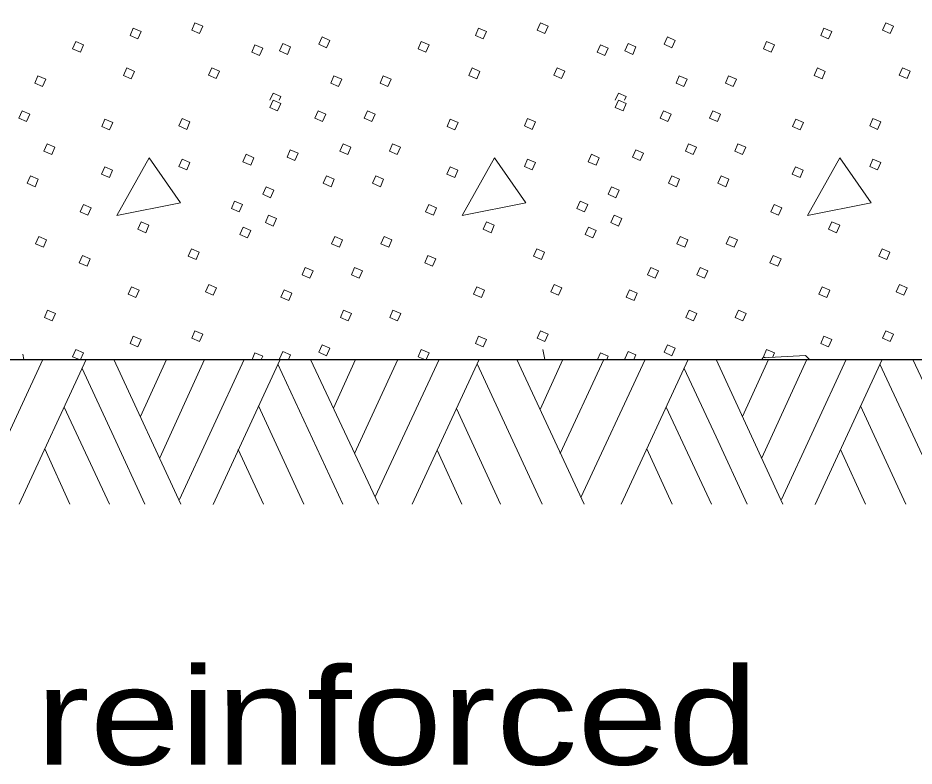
# Model space of a CAD drawing. Extents: x 1083.1 to 1117.1, y 697.4 to 741.4.
# Drawn here: x 1092.828 to 1094.266, y 720.549 to 721.75 of the extents above; entities that cross this region are included whole.
import ezdxf

# ---------------------------------------------------------------- set-up
doc = ezdxf.new("R2010")
doc.units = 0
doc.header["$LTSCALE"] = 0.062
doc.layers.add('1', color=7, linetype='Continuous', lineweight=13)

msp = doc.modelspace()

# ---------------------------------------------------------------- linework, layer by layer
at = {"layer": '1'}
for p, q in [((1093.23258, 721.61833), (1093.23758, 721.62975)), ((1093.78692, 721.61833), (1093.79192, 721.62975)), ((1092.8375, 721.20167), (1092.83575, 721.21042)), ((1093.20392, 721.20167), (1093.20858, 721.2125)), ((1093.67367, 721.20167), (1093.67058, 721.21775)), ((1093.75817, 721.20167), (1093.76292, 721.2125)), ((1092.86833, 721.20167), (1092.76533, 720.9805)), ((1092.9375, 721.20167), (1092.83017, 720.96958)), ((1092.98225, 721.20167), (1093.08958, 720.96958)), ((1093.06658, 721.20167), (1093.02467, 721.11017)), ((1093.12775, 721.20167), (1093.05567, 721.04392)), ((1093.19125, 721.20167), (1093.0875, 720.97683)), ((1093.24892, 721.20167), (1093.14142, 720.96892)), ((1093.24525, 721.1945), (1093.34975, 720.96958)), ((1093.29783, 721.20167), (1093.40675, 720.96958)), ((1093.36992, 721.20167), (1093.33467, 721.12383)), ((1093.43767, 721.20167), (1093.36842, 721.05108)), ((1093.504, 721.20167), (1093.40158, 720.98125)), ((1093.56817, 721.20167), (1093.46067, 720.96958)), ((1093.56525, 721.19517), (1093.66967, 720.96958)), ((1093.62858, 721.20167), (1093.73675, 720.96958)), ((1093.70292, 721.20167), (1093.66608, 721.12175)), ((1093.76842, 721.20167), (1093.69858, 721.05108)), ((1093.83475, 721.20167), (1093.73167, 720.9805)), ((1093.904, 721.20167), (1093.7965, 720.96958)), ((1093.94858, 721.20167), (1094.056, 720.96958)), ((1094.03292, 721.20167), (1093.99117, 721.11017)), ((1094.09417, 721.20167), (1094.02217, 721.04392)), ((1094.15758, 721.20167), (1094.05383, 720.97683)), ((1094.21525, 721.20167), (1094.10792, 720.96892)), ((1094.21167, 721.1945), (1094.31617, 720.96958)), ((1094.26425, 721.20167), (1094.37308, 720.96958)), ((1092.93108, 721.18733), (1092.98225, 721.07775)), ((1093.8975, 721.18733), (1093.94858, 721.07775)), ((1092.90225, 721.12533), (1092.975, 720.96958)), ((1093.21433, 721.12742), (1093.28708, 720.96958)), ((1093.53208, 721.12317), (1093.60275, 720.96958)), ((1093.86858, 721.12533), (1093.94133, 720.96958)), ((1094.18067, 721.12742), (1094.25342, 720.96958)), ((1092.98225, 721.07775), (1093.032, 720.96958)), ((1093.94858, 721.07775), (1093.99833, 720.96958)), ((1092.87125, 721.05825), (1092.91158, 720.96958)), ((1093.18183, 721.05758), (1093.22217, 720.96958)), ((1093.50175, 721.05533), (1093.54075, 720.96958)), ((1093.83758, 721.05825), (1093.878, 720.96958)), ((1094.14825, 721.05758), (1094.18858, 720.96958))]:
    msp.add_line(p, q, dxfattribs=at)
at = {"layer": '1', "lineweight": 25}
for points in [[(1091.06575, 722.92817), (1090.41717, 722.92817), (1090.41717, 721.20167), (1094.915, 721.20167), (1094.915, 722.92817)], [(1090.41717, 722.92817), (1090.41717, 721.20167), (1094.915, 721.20167), (1094.915, 722.92817), (1094.26642, 722.92817)]]:
    msp.add_lwpolyline(points, dxfattribs=at)
at = {"layer": '1'}
for points in [[(1093.11225, 721.74233), (1093.12475, 721.73692), (1093.11958, 721.72517), (1093.10708, 721.7305)], [(1093.66658, 721.74233), (1093.67908, 721.73692), (1093.67392, 721.72517), (1093.66142, 721.7305)], [(1094.22083, 721.74233), (1094.23333, 721.73692), (1094.22817, 721.72517), (1094.21567, 721.7305)], [(1093.01317, 721.734), (1093.02567, 721.72858), (1093.0205, 721.71683), (1093.008, 721.72225)], [(1093.5675, 721.734), (1093.58, 721.72858), (1093.57483, 721.71683), (1093.56233, 721.72225)], [(1094.12183, 721.734), (1094.13433, 721.72858), (1094.12917, 721.71683), (1094.11667, 721.72225)], [(1092.92108, 721.71267), (1092.93358, 721.70725), (1092.92842, 721.69542), (1092.91592, 721.70083)], [(1093.31625, 721.71975), (1093.32875, 721.71433), (1093.32358, 721.7025), (1093.31108, 721.70792)], [(1093.47542, 721.71267), (1093.48792, 721.70725), (1093.48275, 721.69542), (1093.47025, 721.70083)], [(1093.8705, 721.71975), (1093.883, 721.71433), (1093.87783, 721.7025), (1093.86533, 721.70792)], [(1094.02967, 721.71267), (1094.04217, 721.70725), (1094.037, 721.69542), (1094.02458, 721.70083)], [(1093.20858, 721.707), (1093.22108, 721.70158), (1093.21592, 721.68975), (1093.20342, 721.69517)], [(1093.25317, 721.70908), (1093.26567, 721.70367), (1093.2605, 721.69183), (1093.248, 721.69725)], [(1093.76292, 721.707), (1093.77542, 721.70158), (1093.77025, 721.68975), (1093.75775, 721.69517)], [(1093.8075, 721.70908), (1093.82, 721.70367), (1093.81483, 721.69183), (1093.80233, 721.69725)], [(1093.00275, 721.66992), (1093.01525, 721.6645), (1093.01008, 721.65267), (1092.99758, 721.65808)], [(1093.13917, 721.67017), (1093.15167, 721.66475), (1093.1465, 721.65292), (1093.134, 721.65833)], [(1093.55708, 721.66992), (1093.56958, 721.6645), (1093.56442, 721.65267), (1093.55192, 721.65808)], [(1093.69342, 721.67017), (1093.70592, 721.66475), (1093.70075, 721.65292), (1093.68825, 721.65833)], [(1094.11142, 721.66992), (1094.12392, 721.6645), (1094.11875, 721.65267), (1094.10625, 721.65808)], [(1094.24775, 721.67017), (1094.26025, 721.66475), (1094.25508, 721.65292), (1094.24258, 721.65833)], [(1092.86017, 721.65742), (1092.87267, 721.652), (1092.8675, 721.64017), (1092.855, 721.64558)], [(1093.33525, 721.65742), (1093.34775, 721.652), (1093.34258, 721.64017), (1093.33008, 721.64558)], [(1093.4145, 721.65742), (1093.427, 721.652), (1093.42183, 721.64017), (1093.40933, 721.64558)], [(1093.88958, 721.65742), (1093.90208, 721.652), (1093.89692, 721.64017), (1093.88442, 721.64558)], [(1093.96883, 721.65742), (1093.98133, 721.652), (1093.97617, 721.64017), (1093.96367, 721.64558)], [(1093.23758, 721.61833), (1093.25008, 721.61292), (1093.24492, 721.60108), (1093.23242, 721.6065)], [(1093.79192, 721.61833), (1093.80442, 721.61292), (1093.79925, 721.60108), (1093.78675, 721.6065)], [(1092.83467, 721.60133), (1092.84717, 721.59592), (1092.842, 721.58417), (1092.8295, 721.5895)], [(1093.30983, 721.60133), (1093.32233, 721.59592), (1093.31717, 721.58417), (1093.30467, 721.5895)], [(1093.389, 721.60133), (1093.4015, 721.59592), (1093.39633, 721.58417), (1093.38383, 721.5895)], [(1093.86408, 721.60133), (1093.87658, 721.59592), (1093.87142, 721.58417), (1093.85892, 721.5895)], [(1093.94333, 721.60133), (1093.95583, 721.59592), (1093.95067, 721.58417), (1093.93817, 721.5895)], [(1092.96783, 721.58792), (1092.98025, 721.58258), (1092.97517, 721.57075), (1092.96267, 721.57617)], [(1093.09175, 721.58858), (1093.10425, 721.58325), (1093.09908, 721.57142), (1093.08658, 721.57683)], [(1093.52208, 721.58792), (1093.53458, 721.58258), (1093.52942, 721.57075), (1093.51692, 721.57617)], [(1093.64608, 721.58858), (1093.65858, 721.58325), (1093.65342, 721.57142), (1093.64092, 721.57683)], [(1094.07642, 721.58792), (1094.08892, 721.58258), (1094.08375, 721.57075), (1094.07125, 721.57617)], [(1094.20042, 721.58858), (1094.21283, 721.58325), (1094.20775, 721.57142), (1094.19525, 721.57683)], [(1092.87508, 721.54833), (1092.88758, 721.54292), (1092.88242, 721.53108), (1092.86992, 721.5365)], [(1093.26525, 721.53842), (1093.27775, 721.533), (1093.27258, 721.52117), (1093.26008, 721.52658)], [(1093.35017, 721.54833), (1093.36267, 721.54292), (1093.3575, 721.53108), (1093.345, 721.5365)], [(1093.42942, 721.54833), (1093.44192, 721.54292), (1093.43675, 721.53108), (1093.42425, 721.5365)], [(1093.81958, 721.53842), (1093.83208, 721.533), (1093.82692, 721.52117), (1093.81442, 721.52658)], [(1093.9045, 721.54833), (1093.917, 721.54292), (1093.91183, 721.53108), (1093.89933, 721.5365)], [(1093.98375, 721.54833), (1093.99625, 721.54292), (1093.99108, 721.53108), (1093.97858, 721.5365)], [(1093.03883, 721.52592), (1092.98658, 721.43333), (1093.08892, 721.45325)], [(1093.19442, 721.53133), (1093.20692, 721.52592), (1093.20175, 721.51408), (1093.18925, 721.5195)], [(1093.59317, 721.52592), (1093.54092, 721.43333), (1093.64325, 721.45325)], [(1093.74875, 721.53133), (1093.76125, 721.52592), (1093.75608, 721.51408), (1093.74358, 721.5195)], [(1094.1475, 721.52592), (1094.09525, 721.43333), (1094.19758, 721.45325)], [(1092.96758, 721.51125), (1092.98, 721.50583), (1092.97483, 721.494), (1092.96242, 721.49942)], [(1093.09175, 721.5235), (1093.10425, 721.51808), (1093.09908, 721.50625), (1093.08658, 721.51167)], [(1093.52183, 721.51125), (1093.53433, 721.50583), (1093.52917, 721.494), (1093.51667, 721.49942)], [(1093.64608, 721.5235), (1093.65858, 721.51808), (1093.65342, 721.50625), (1093.64092, 721.51167)], [(1094.07617, 721.51125), (1094.08867, 721.50583), (1094.0835, 721.494), (1094.071, 721.49942)], [(1094.20042, 721.5235), (1094.21283, 721.51808), (1094.20775, 721.50625), (1094.19525, 721.51167)], [(1092.84817, 721.49658), (1092.86067, 721.49117), (1092.8555, 721.47933), (1092.843, 721.48475)], [(1093.32333, 721.49658), (1093.33575, 721.49117), (1093.33058, 721.47933), (1093.31817, 721.48475)], [(1093.4025, 721.49658), (1093.415, 721.49117), (1093.40983, 721.47933), (1093.39733, 721.48475)], [(1093.87758, 721.49658), (1093.89008, 721.49117), (1093.88492, 721.47933), (1093.87242, 721.48475)], [(1093.95683, 721.49658), (1093.96933, 721.49117), (1093.96417, 721.47933), (1093.95167, 721.48475)], [(1093.22625, 721.47892), (1093.23875, 721.4735), (1093.23358, 721.46167), (1093.22108, 721.46708)], [(1093.78058, 721.47892), (1093.79308, 721.4735), (1093.78792, 721.46167), (1093.77542, 721.46708)], [(1093.17592, 721.45625), (1093.18842, 721.45083), (1093.18325, 721.43908), (1093.17075, 721.44442)], [(1093.73025, 721.45625), (1093.74275, 721.45083), (1093.73758, 721.43908), (1093.72508, 721.44442)], [(1092.93317, 721.45058), (1092.94567, 721.44517), (1092.9405, 721.43342), (1092.928, 721.43883)], [(1093.4875, 721.45058), (1093.5, 721.44517), (1093.49483, 721.43342), (1093.48233, 721.43883)], [(1094.04175, 721.45058), (1094.05425, 721.44517), (1094.04908, 721.43342), (1094.03658, 721.43883)], [(1093.2305, 721.43342), (1093.243, 721.428), (1093.23783, 721.41617), (1093.22533, 721.42158)], [(1093.78483, 721.43342), (1093.79733, 721.428), (1093.79217, 721.41617), (1093.77967, 721.42158)], [(1093.02583, 721.42275), (1093.03833, 721.41733), (1093.03317, 721.4055), (1093.02067, 721.41092)], [(1093.18942, 721.41425), (1093.20192, 721.40883), (1093.19675, 721.397), (1093.18425, 721.40242)], [(1093.58017, 721.42275), (1093.59267, 721.41733), (1093.5875, 721.4055), (1093.575, 721.41092)], [(1093.74375, 721.41425), (1093.75625, 721.40883), (1093.75108, 721.397), (1093.73858, 721.40242)], [(1094.1345, 721.42275), (1094.147, 721.41733), (1094.14183, 721.4055), (1094.12933, 721.41092)], [(1092.86158, 721.39942), (1092.87408, 721.394), (1092.86892, 721.38217), (1092.85642, 721.38758)], [(1093.33667, 721.39942), (1093.34917, 721.394), (1093.344, 721.38217), (1093.3315, 721.38758)], [(1093.41592, 721.39942), (1093.42842, 721.394), (1093.42325, 721.38217), (1093.41075, 721.38758)], [(1093.891, 721.39942), (1093.9035, 721.394), (1093.89833, 721.38217), (1093.88583, 721.38758)], [(1093.97025, 721.39942), (1093.98275, 721.394), (1093.97758, 721.38217), (1093.96508, 721.38758)], [(1092.93175, 721.36892), (1092.94425, 721.3635), (1092.93908, 721.35167), (1092.92658, 721.35708)], [(1093.10658, 721.37958), (1093.11908, 721.37417), (1093.11392, 721.36233), (1093.10142, 721.36775)], [(1093.48608, 721.36892), (1093.49858, 721.3635), (1093.49342, 721.35167), (1093.48092, 721.35708)], [(1093.66092, 721.37958), (1093.67342, 721.37417), (1093.66825, 721.36233), (1093.65575, 721.36775)], [(1094.04033, 721.36892), (1094.05283, 721.3635), (1094.04767, 721.35167), (1094.03517, 721.35708)], [(1094.21517, 721.37958), (1094.22767, 721.37417), (1094.2225, 721.36233), (1094.21, 721.36775)], [(1093.28933, 721.34983), (1093.30183, 721.34442), (1093.29667, 721.33258), (1093.28417, 721.338)], [(1093.3685, 721.34983), (1093.381, 721.34442), (1093.37583, 721.33258), (1093.36333, 721.338)], [(1093.84367, 721.34983), (1093.85617, 721.34442), (1093.851, 721.33258), (1093.8385, 721.338)], [(1093.92283, 721.34983), (1093.93533, 721.34442), (1093.93017, 721.33258), (1093.91767, 721.338)], [(1093.01025, 721.31867), (1093.02275, 721.31325), (1093.01758, 721.30142), (1093.00508, 721.30683)], [(1093.13425, 721.32217), (1093.14675, 721.31675), (1093.14158, 721.30492), (1093.12908, 721.31033)], [(1093.25533, 721.31367), (1093.26783, 721.30825), (1093.26267, 721.2965), (1093.25017, 721.30183)], [(1093.56458, 721.31867), (1093.57708, 721.31325), (1093.57192, 721.30142), (1093.55942, 721.30683)], [(1093.6885, 721.32217), (1093.701, 721.31675), (1093.69583, 721.30492), (1093.68333, 721.31033)], [(1093.80967, 721.31367), (1093.82217, 721.30825), (1093.817, 721.2965), (1093.8045, 721.30183)], [(1094.11892, 721.31867), (1094.13142, 721.31325), (1094.12625, 721.30142), (1094.11375, 721.30683)], [(1094.24283, 721.32217), (1094.25533, 721.31675), (1094.25017, 721.30492), (1094.23767, 721.31033)], [(1092.87575, 721.28117), (1092.88825, 721.27575), (1092.88308, 721.26392), (1092.87058, 721.26933)], [(1093.35083, 721.28117), (1093.36333, 721.27575), (1093.35817, 721.26392), (1093.34567, 721.26933)], [(1093.43008, 721.28117), (1093.44258, 721.27575), (1093.43742, 721.26392), (1093.42492, 721.26933)], [(1093.90517, 721.28117), (1093.91767, 721.27575), (1093.9125, 721.26392), (1093.9, 721.26933)], [(1093.98442, 721.28117), (1093.99692, 721.27575), (1093.99175, 721.26392), (1093.97925, 721.26933)], [(1093.01317, 721.23958), (1093.02567, 721.23417), (1093.0205, 721.22233), (1093.008, 721.22775)], [(1093.11225, 721.24792), (1093.12475, 721.2425), (1093.11958, 721.23067), (1093.10708, 721.23608)], [(1093.5675, 721.23958), (1093.58, 721.23417), (1093.57483, 721.22233), (1093.56233, 721.22775)], [(1093.66658, 721.24792), (1093.67908, 721.2425), (1093.67392, 721.23067), (1093.66142, 721.23608)], [(1094.12183, 721.23958), (1094.13433, 721.23417), (1094.12917, 721.22233), (1094.11667, 721.22775)], [(1094.22083, 721.24792), (1094.23333, 721.2425), (1094.22817, 721.23067), (1094.21567, 721.23608)], [(1093.31625, 721.22525), (1093.32875, 721.21983), (1093.32358, 721.208), (1093.31108, 721.21342)], [(1093.8705, 721.22525), (1093.883, 721.21983), (1093.87783, 721.208), (1093.86533, 721.21342)]]:
    msp.add_lwpolyline(points, close=True, dxfattribs=at)
for points in [[(1093.23758, 721.62975), (1093.25008, 721.62433), (1093.2475, 721.61833)], [(1093.79192, 721.62975), (1093.80442, 721.62433), (1093.80183, 721.61833)], [(1092.92667, 721.20167), (1092.91592, 721.20633), (1092.92108, 721.21817)], [(1092.92108, 721.21817), (1092.93358, 721.21275), (1092.92875, 721.20167)], [(1093.20858, 721.2125), (1093.22108, 721.20708), (1093.21875, 721.20167)], [(1093.2505, 721.20167), (1093.248, 721.20275), (1093.25317, 721.21458)], [(1093.25317, 721.21458), (1093.26567, 721.20917), (1093.26242, 721.20167)], [(1093.481, 721.20167), (1093.47025, 721.20633), (1093.47542, 721.21817)], [(1093.47542, 721.21817), (1093.48792, 721.21275), (1093.48308, 721.20167)], [(1093.76292, 721.2125), (1093.77542, 721.20708), (1093.77308, 721.20167)], [(1093.80483, 721.20167), (1093.80233, 721.20275), (1093.8075, 721.21458)], [(1093.8075, 721.21458), (1093.82, 721.20917), (1093.81667, 721.20167)], [(1094.02183, 721.20167), (1094.02375, 721.20442), (1094.09233, 721.20817), (1094.09858, 721.20167)], [(1094.02842, 721.20467), (1094.02458, 721.20633), (1094.02967, 721.21817)], [(1094.02967, 721.21817), (1094.04217, 721.21275), (1094.03892, 721.20525)]]:
    msp.add_lwpolyline(points, dxfattribs=at)

# ---------------------------------------------------------------- texts
at = {"layer": '1', "width": 1.25}
msp.add_text('Plain or reinforced', height=0.156, dxfattribs=at).set_placement((1091.9, 720.55125))

doc.saveas('drawing.dxf')
